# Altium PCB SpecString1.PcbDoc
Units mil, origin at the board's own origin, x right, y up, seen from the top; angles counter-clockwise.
Board outline 13135 x 12270 mil, 2 copper layers (Top Layer, Bottom Layer); 15 components, 16 nets, 35 pads, 6 vias.
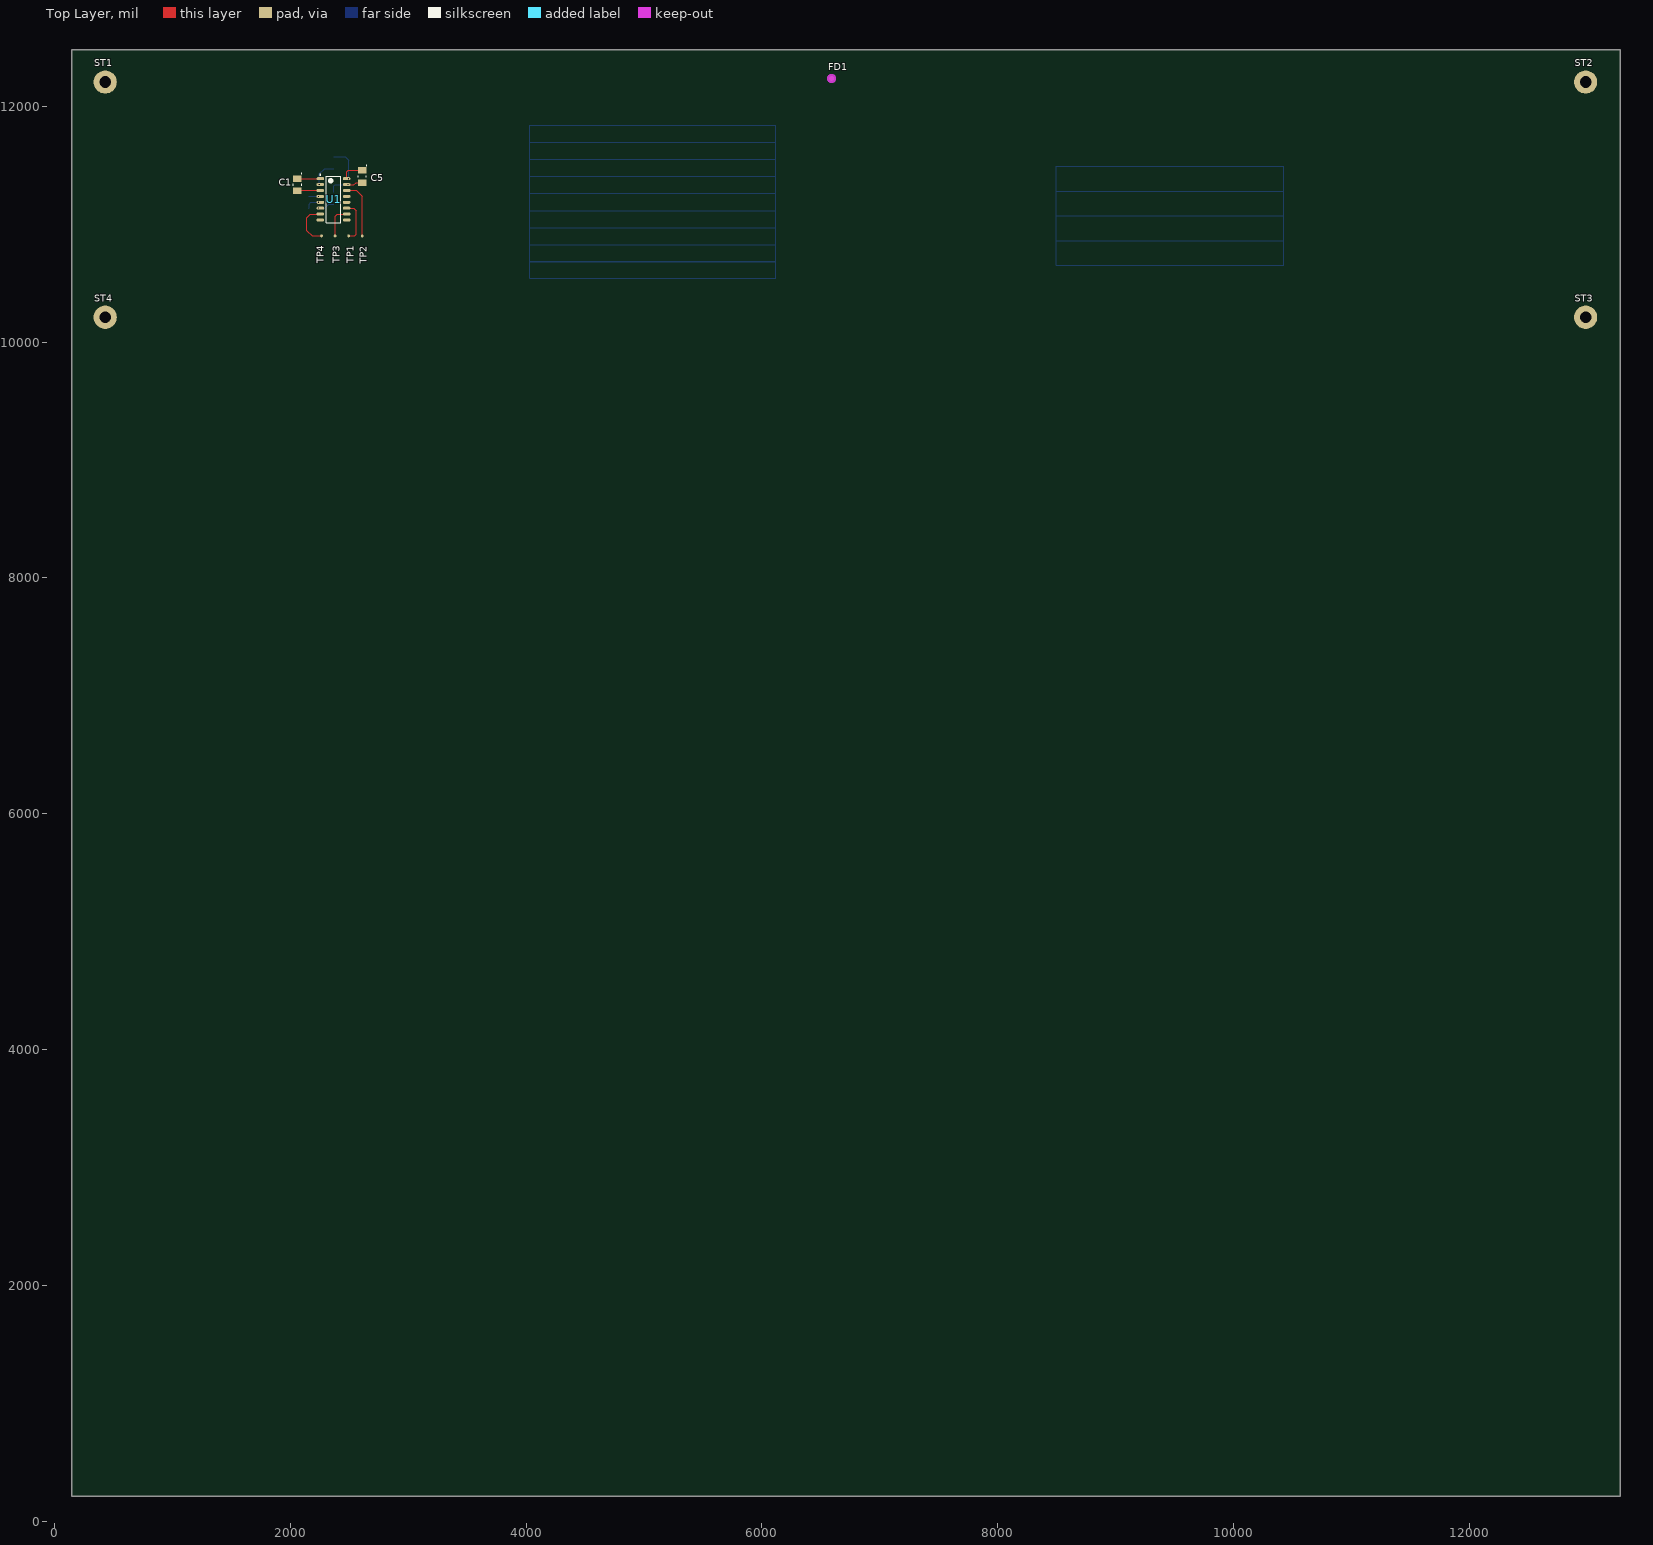
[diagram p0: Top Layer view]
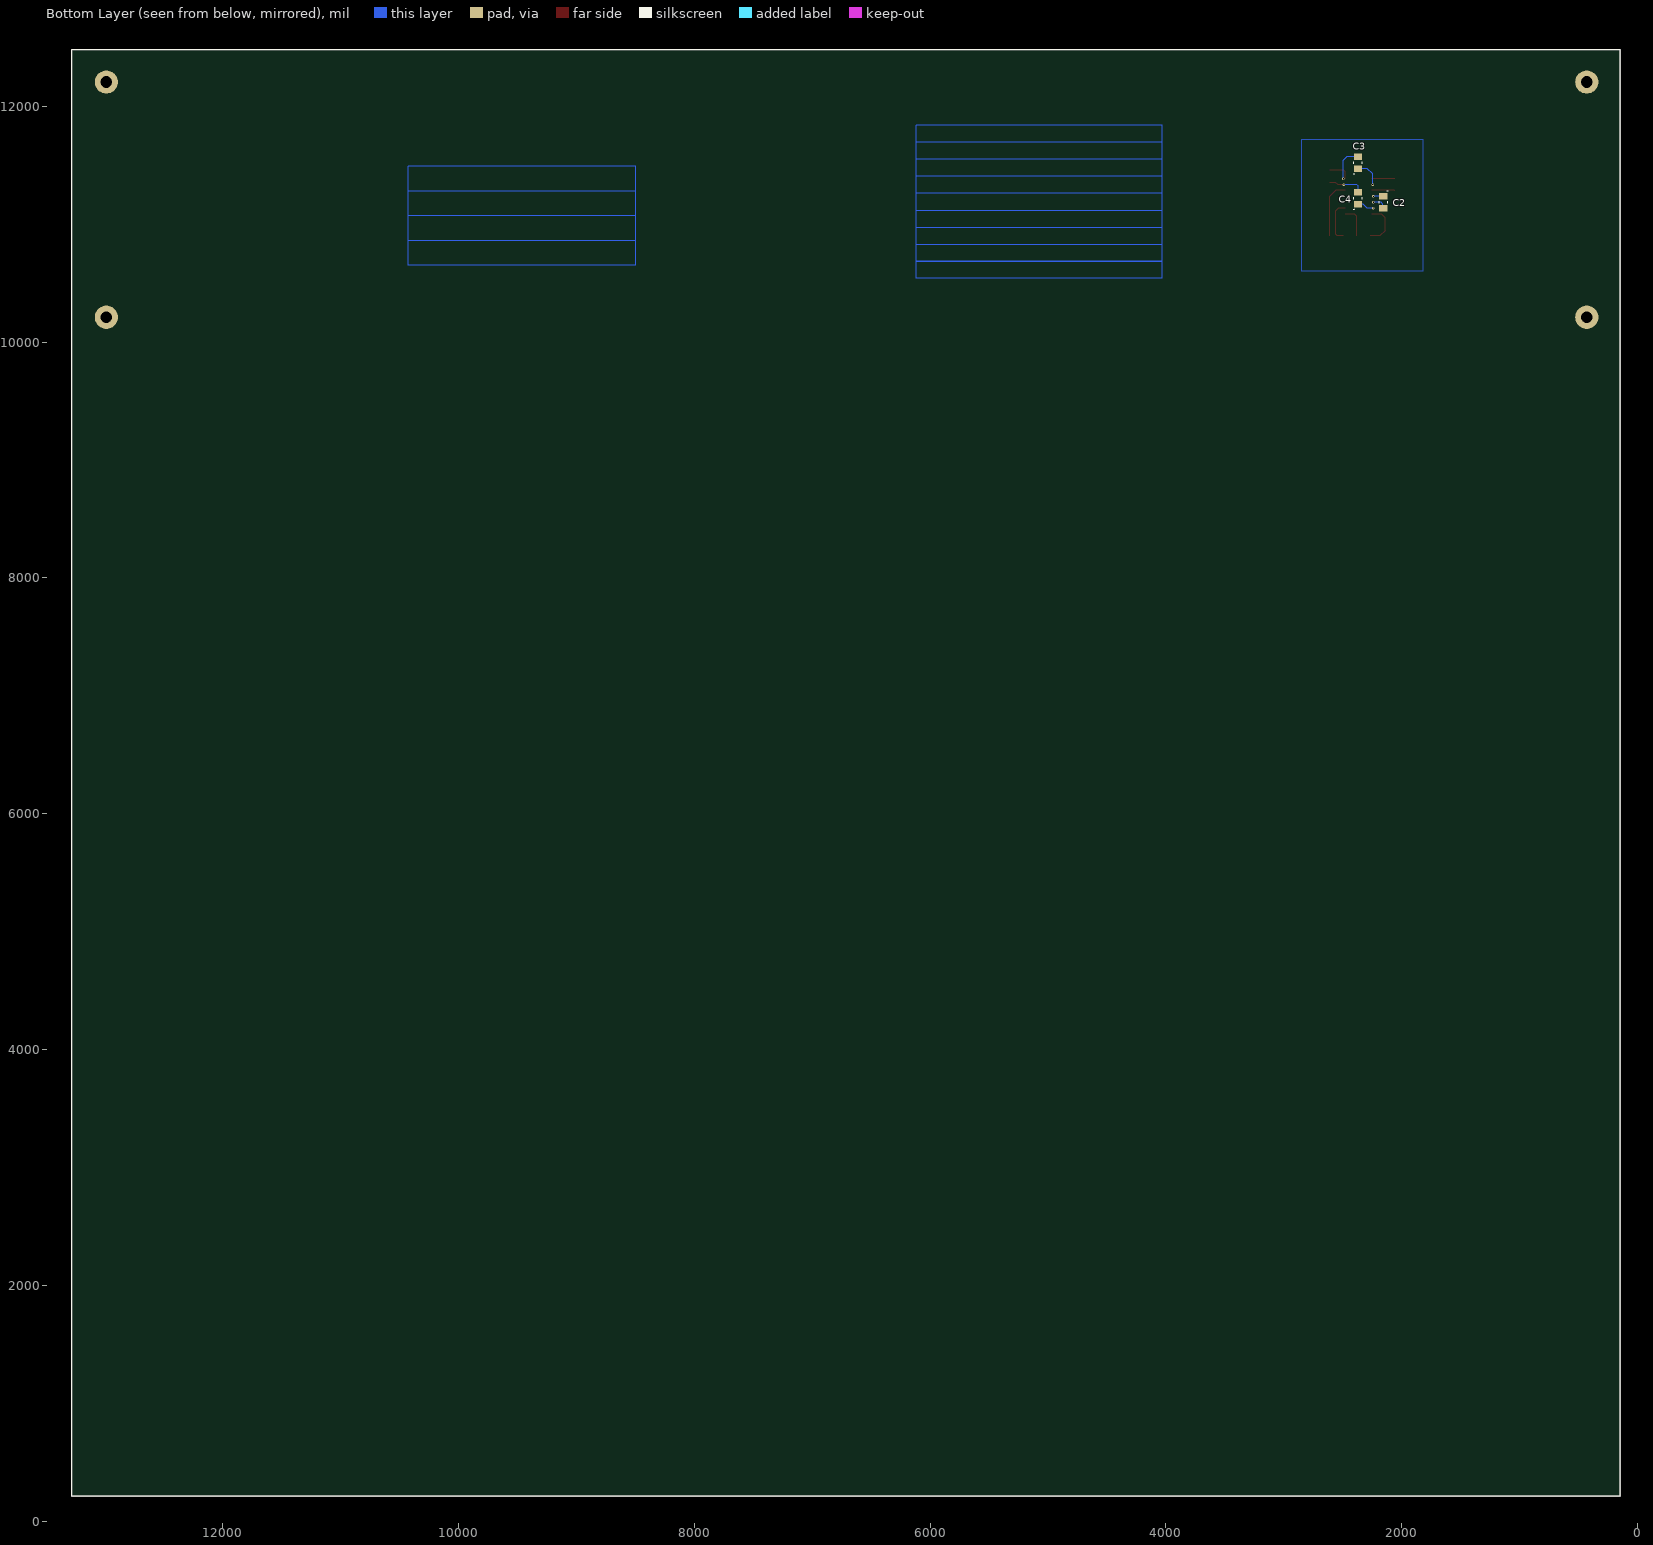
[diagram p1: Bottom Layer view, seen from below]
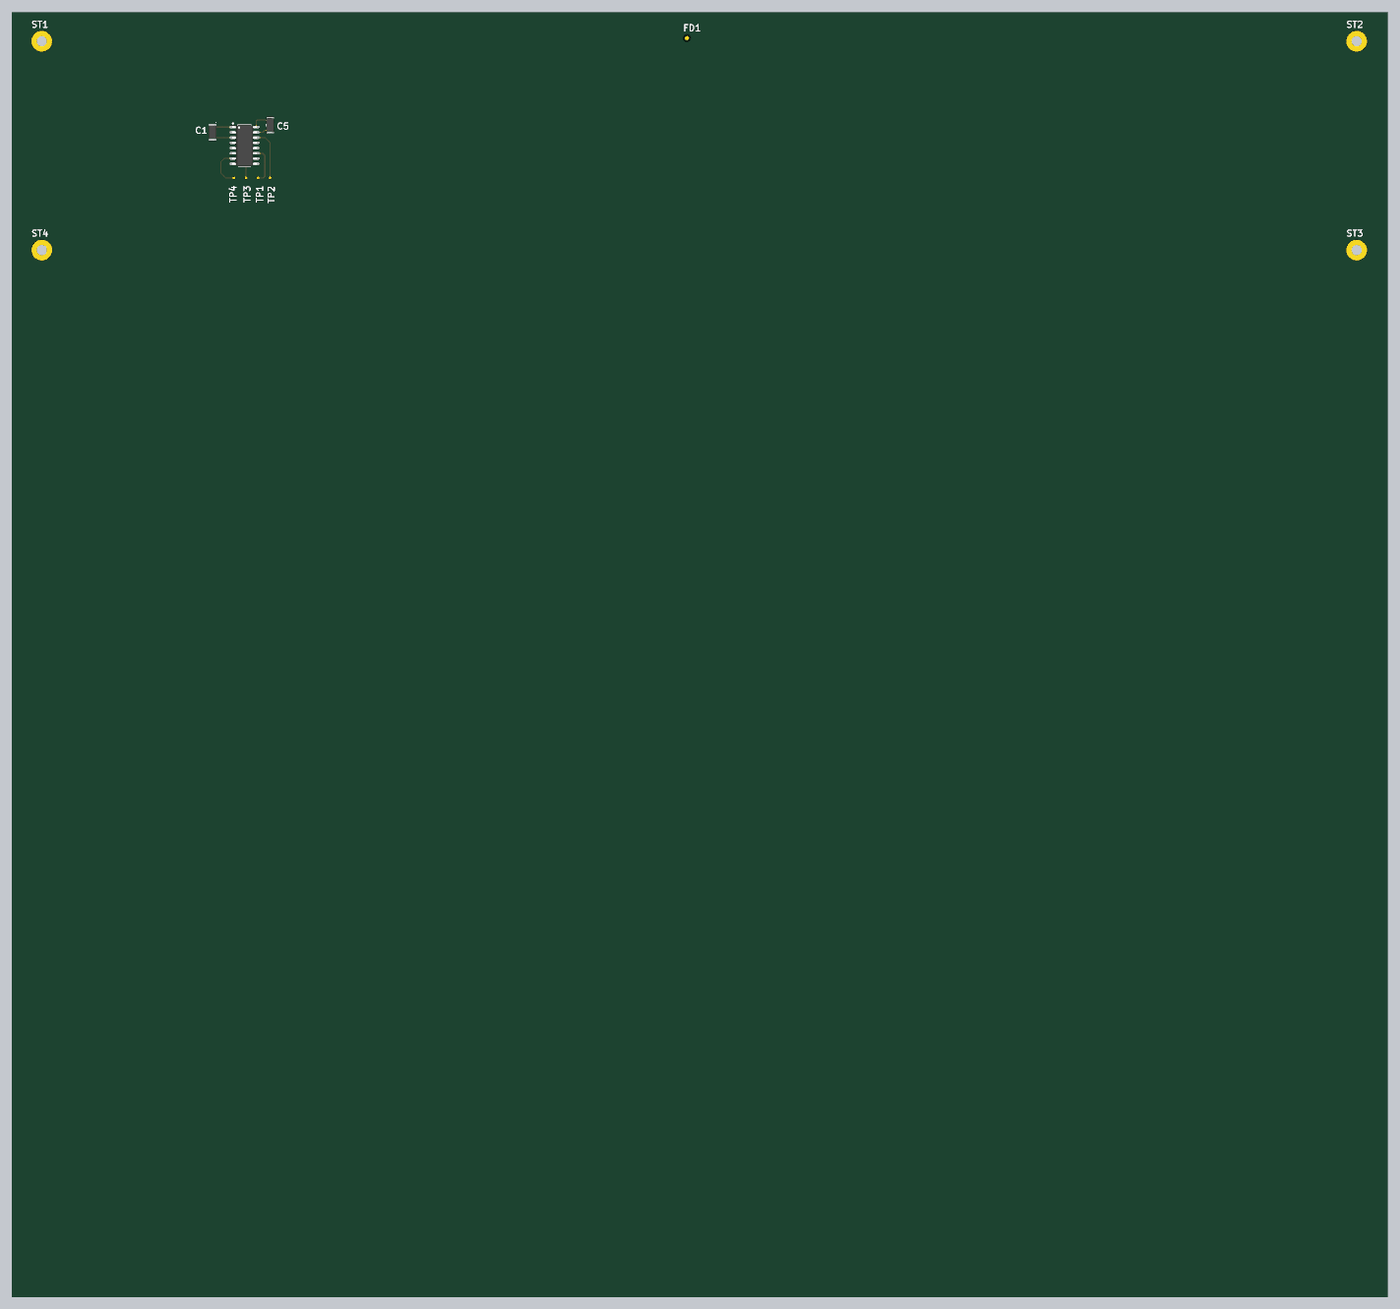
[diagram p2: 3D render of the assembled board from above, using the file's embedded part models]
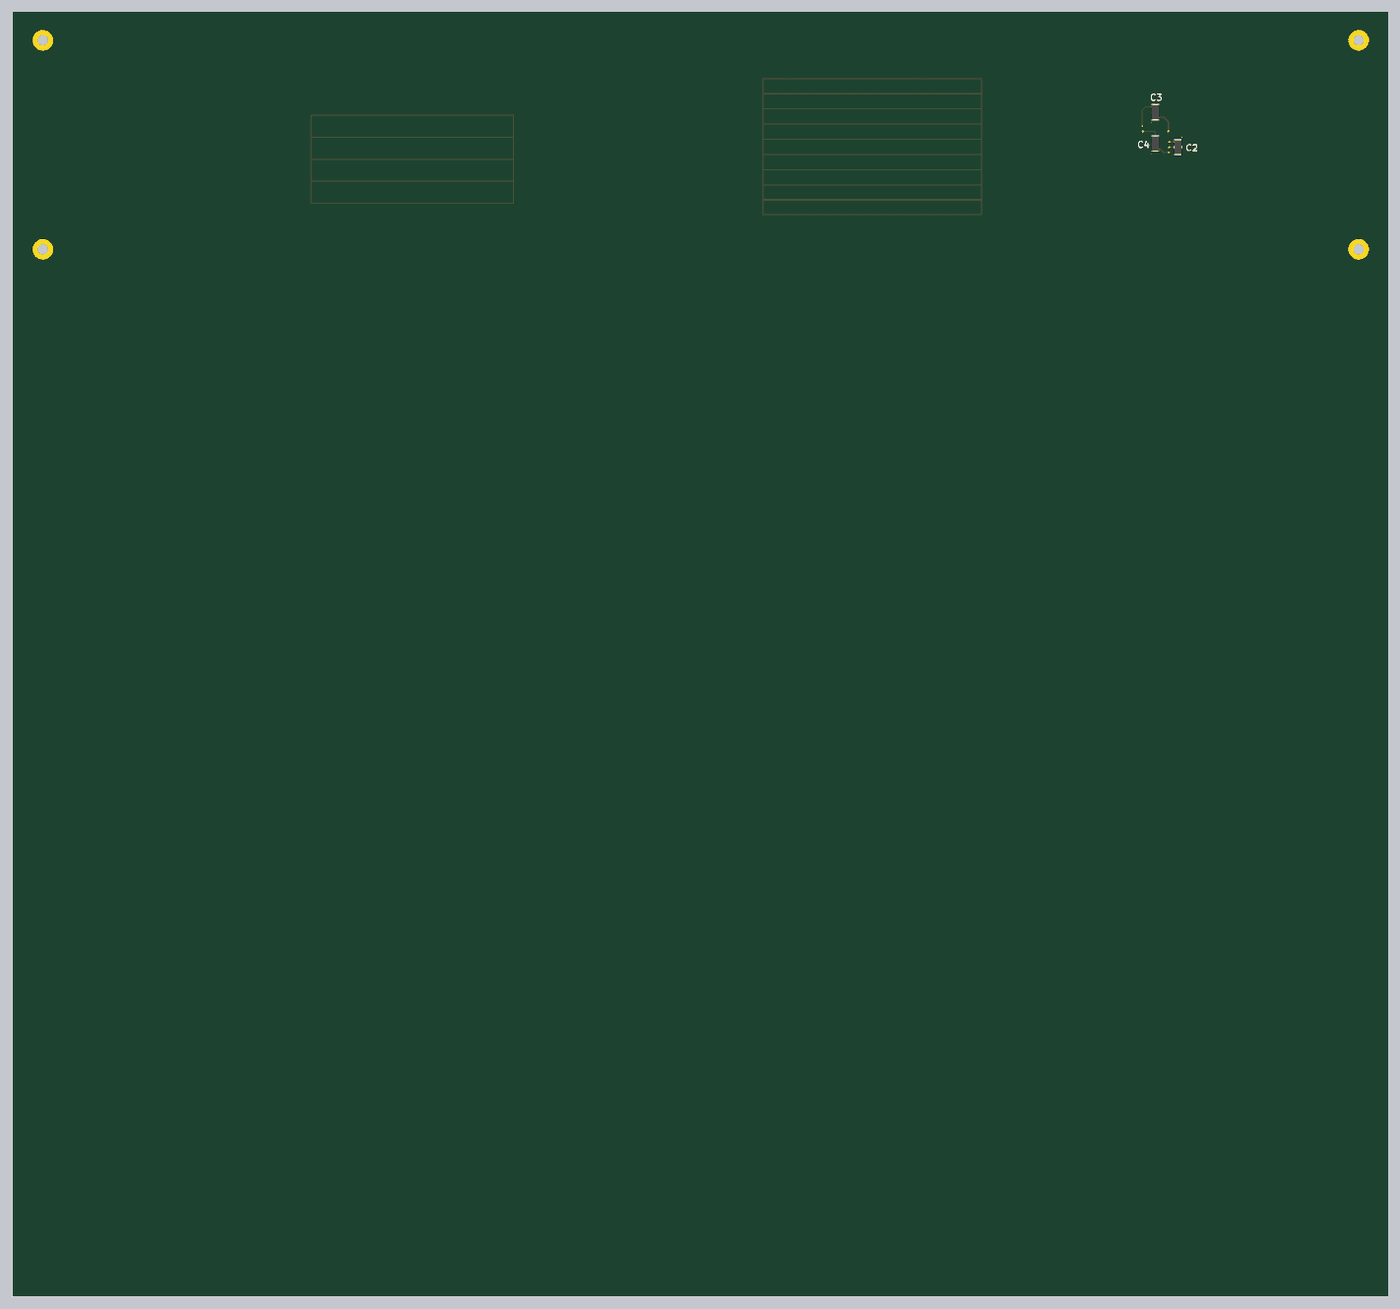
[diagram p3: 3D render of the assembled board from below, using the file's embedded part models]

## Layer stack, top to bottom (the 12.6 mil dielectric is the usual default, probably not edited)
Top Solder: solder mask 0.4, Solder Resist, Dk 3.5
Top Layer: signal copper 1.4
Dielectric 1: dielectric 12.6, FR-4, Dk 4.8
Bottom Layer: signal copper 1.4
Bottom Solder: solder mask 0.4, Solder Resist, Dk 3.5

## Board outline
145,210 145,12480 13280,12480 13280,210

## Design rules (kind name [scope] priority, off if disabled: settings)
Clearance [All] p1: gap=10 ignorepadtopadclearanceinfootprint=FALSE except(0: Arc-Hole Track-Hole SMDPad-Hole THPad-Hole Via-Hole Fill-Hole Poly-Hole Region-Hole Text-Hole)
PolygonConnect [All] p1: connectstyle=Relief reliefconductorwidth=10 reliefentries=4 polygonreliefangle="90 Angle" airgapwidth=10
RoutingVias [All] p1: holewidth=8 width=20 viastyle="Through Hole" minholewidth=6 minwidth=18 maxholewidth=12 maxwidth=50
SolderMaskExpansion [All] p1: expansion=4 istentingtop=FALSE
Width [All] p1: maxlimit=10 minlimit=10 preferedwidth=10
30 further rules are at their usual default settings.

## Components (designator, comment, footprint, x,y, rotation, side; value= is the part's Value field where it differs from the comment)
C1 "KYOCERA AVX-TAJA105K035RNJ" CAPMP3217X18-T_V 2060,11335 r270 top value=1µF
C2 "KYOCERA AVX-TAJA105K035RNJ" CAPMP3217X18-T_V 2155,11185 r270 bottom value=1µF
C3 "KYOCERA AVX-TAJA105K035RNJ" CAPMP3217X18-T_V 2370,11520 r90 bottom value=1µF
C4 "KYOCERA AVX-TAJA105K035RNJ" CAPMP3217X18-T_V 2370,11220 r90 bottom value=1µF
C5 "KYOCERA AVX-TAJA105K035RNJ" CAPMP3217X18-T_V 2610,11403.82 r270 top value=1µF
FD1 "FID1X2R" FID1X2R 6590,12235 r0 top
ST1 "PTH-M2D5X5" PTH-M2D5X5 430,12205 r0 top
ST2 "PTH-M2D5X5" PTH-M2D5X5 12985,12205 r0 top
ST3 "PTH-M2D5X5" PTH-M2D5X5 12985,10210 r0 top
ST4 "PTH-M2D5X5" PTH-M2D5X5 430,10210 r0 top
TP1 "TPAD6R" TP06R 2495,10900 r90 top
TP2 "TPAD6R" TP06R 2610,10900 r90 top
TP3 "TPAD6R" TP06R 2380,10900 r90 top
TP4 "TPAD6R" TP06R 2265,10900 r90 top
U1 "MAX232CSE+" MAXM-S16+5_M 2366.22,11210 r0 top

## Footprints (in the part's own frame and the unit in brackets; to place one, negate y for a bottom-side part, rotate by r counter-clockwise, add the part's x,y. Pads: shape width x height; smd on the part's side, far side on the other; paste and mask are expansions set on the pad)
CAPMP3217X18-T_V [mm] "Molded Capacitor, 2-Leads, Body 3.40x1.8mm"
  rect 1.4x1.8 smd: 1(-1.3,0) 2(1.3,0)
  silkscreen extent -2.45,-0.9 0.2,0.95, body extent -1.92,-0.9 1.92,0.9, height 1.8
FID1X2R [mm] "Fiducial - Round 1x2mm"
  round 1 smd paste-0.5 mask+0.5: 0(0,0)
  Top Layer keep-out circle w1: c0,0 r0.5
MAXM-S16+5_M [mm] "SOIC, 16-Leads, Body 10x4mm, Pitch 1.27mm, IPC Low Density"
  oval 1.65x0.65 smd: 1(-2.825,4.445) 2(-2.825,3.175) 3(-2.825,1.905) 4(-2.825,0.635) 5(-2.825,-0.635) 6(-2.825,-1.905) 7(-2.825,-3.175) 8(-2.825,-4.445) 9(2.825,-4.445) 10(2.825,-3.175) 11(2.825,-1.905) 12(2.825,-0.635) 13(2.825,0.635) 14(2.825,1.905) 15(2.825,3.175) 16(2.825,4.445)
  silkscreen extent -2.95,-5 1.6,5.44, body extent -3,-5 3,5, height 1.75
PTH-M2D5X5 [mm]
  round 5 hole 2.5: 1(0,0)
TP06R [mm] "Testpoint, round, d=0.6mm"
  round 0.6 smd paste-1: 1(0,0)

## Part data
C1 C2 C3 C4 C5: library part CMP-001-00040-7, "Standard Tantalum, 1 uF, +/- 10%, 35 V, -55 to 125 degC, 1206 (3216 Metric), RoHS, Tape and Reel", Capacitor Type=Tantalum, Case/Package=1206, Manufacturer=AVX, Max Operating Temperature=125°C, Min Operating Temperature=-55°C, Package Description="2-Pin Surface Mount Device, Body 3.2 x 1.65 mm", Package Quantity=2000, Package Reference=CAPMP3217X18-T, Resistance=7.5Ohm, Tolerance=10%, Voltage Rating=35V
FD1: library part CMP-00028-00005-1, "Fiducial - Round 1x2mm"
ST1 ST2 ST3 ST4: library part CMP-00028-00004-1, "M2 PTH (2.5mm), 5mm pad"
TP1 TP2 TP3 TP4: library part CMP-00028-00002-1, "0.6mm round"
U1: library part CMP-00024-00004-1, "Multichannel RS-232 Driver/Receiver, 5 V, 0 to 70 degC, 16-Pin SOIC (S16+3), RoHS, Tube", Case/Package=SOIC, Manufacturer=Maxim, Max Operating Temperature=70°C, Max Supply Voltage=5.5V, Min Operating Temperature=0°C, Min Supply Voltage=4.5V, Nominal Supply Current=10mA, Nominal Supply Voltage=5V, Package Description="16-Pin Small Outline Integrated Circuit, Body 9.9 x 3.9 mm, Pitch 1.27 mm", Package Quantity=50, Package Reference=S16+5, Package Version="Rev. G, 01/2016"

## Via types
v1: diameter 20, hole 8, Top Layer to Bottom Layer, 6 vias

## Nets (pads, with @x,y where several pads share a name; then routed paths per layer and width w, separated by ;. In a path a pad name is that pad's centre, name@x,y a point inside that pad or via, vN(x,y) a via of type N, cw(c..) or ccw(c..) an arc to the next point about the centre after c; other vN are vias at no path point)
+5V: C3.2 C5.1 U1.16 | length 488.1
  Top Layer w10: U1.16 2477.44,11442.44 2490,11455 C5.1
  Bottom Layer w10: C3.2 2371.18,11570 2465,11570 2495,11540 v1(2495,11385)
GND: C4.2 C5.2 U1.15 | length 317.8
  Top Layer w10: U1.15 v1(2490,11335) 2540,11335 2557.64,11352.64 C5.2
  Bottom Layer w10: C4.2 2370,11325 2380,11335 v1(2490,11335)
NetC1_1: C1.1 U1.1 | length 195.5
  Top Layer w10: C1.1 2061.18,11385 U1.1
NetC1_2: C1.2 U1.3 | length 195.5
  Top Layer w10: C1.2 2061.18,11285 U1.3
NetC2_1: C2.1 U1.4 | length 85.5
  Bottom Layer w10: C2.1 2156.18,11235 v1(2240,11235)
NetC2_2: C2.2 U1.5 | length 124.5
  Bottom Layer w10: C2.2 2160,11138.82 2160,11170 2175,11185 v1(2240,11185)
NetC3_1: C3.1 U1.2 | length 233.7
  Bottom Layer w10: v1(2245.6,11335.2) 2245.6,11425.6 2290,11470 2368.82,11470 C3.1
NetC4_1: C4.1 U1.6 | length 144
  Bottom Layer w10: v1(2240,11135) 2290,11135 2323.82,11168.82 C4.1
R1_In: U1.13
R1_Out: U1.12
R2_In: U1.8
R2_Out: U1.9
"T1 _In": TP1.1 U1.11 | length 362.1
  Top Layer w10: U1.11 2540,11135 2560,11115 2560,10915 2545,10900 TP1.1
T1_Out: TP2.1 U1.14 | length 488.3
  Top Layer w10: U1.14 2560,11285 2610,11235 TP2.1
T2_In: TP3.1 U1.10 | length 270.7
  Top Layer w10: TP3.1 2380,11065 2400,11085 U1.10
T2_Out: TP4.1 U1.7 | length 381.1
  Top Layer w10: U1.7 2170,11085 2140,11055 2140,10945 2185,10900 TP4.1
pads on no net: FD1.0 ST1.1 ST2.1 ST3.1 ST4.1
copper on no net: | length 57260
  Bottom Layer w10: 4030,10825 6115,10825 ; 4030,10825 4030,10970 ; 4030,10825 6115,10825 ; 4030,10825 4030,10680 6115,10680 6115,10825 ; 4030,10970 6115,10970 ; 4030,10970 4030,11115 ; 4030,10970 6115,10970 ; 4030,11115 6115,11115 ; 4030,11115 6115,11115 ; 4030,11115 4030,11260 ; 4030,11260 6115,11260 ; 4030,11260 4030,11405 ; 4030,11260 6115,11260 ; 4030,11405 6115,11405 ; 4030,11405 6115,11405 ; 4030,11405 4030,11550 ; 4030,11550 6115,11550 ; 4030,11550 4030,11695 ; 4030,11550 6115,11550 ; 4030,11695 6115,11695 ; 4030,11695 4030,11840 6115,11840 6115,11695 ; 4030,11695 6115,11695 ; 6115,10825 6115,10970 ; 6115,10970 6115,11115 ; 6115,11115 6115,11260 ; 6115,11260 6115,11405 ; 6115,11405 6115,11550 ; 6115,11550 6115,11695 ; 8495,10860 10425,10860 ; 8495,10860 8495,10650 10425,10650 10425,10860 ; 8495,10860 10425,10860 ; 8495,10860 8495,11070 ; 8495,11070 10425,11070 ; 8495,11070 8495,11280 ; 8495,11070 10425,11070 ; 8495,11280 10425,11280 ; 8495,11280 10425,11280 ; 8495,11280 8495,11490 10425,11490 10425,11280 ; 10425,10860 10425,11070 ; 10425,11070 10425,11280 ; 4030,10540 6115,10540 6115,10685 4030,10685 4030,10540

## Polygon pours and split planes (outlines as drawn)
GND on Bottom Layer "GND_L02_P000" (solid, pour order 0): 1815,11715 2850,11715 2850,10605 1815,10605

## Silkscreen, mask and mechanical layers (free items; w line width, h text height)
Bottom Overlay:
  lines w10: 145,210 13280,210 13280,12480 145,12480 145,210 ; 145,2310 145,2325 145,2310
Mechanical 1:
  drawing of 816 lines, arcs and shapes, not listed
  text "Value" at 2810,9980 h60
  text "Notes" at 7480,9980 h60
  text "String Name" at 1279.73,9969.99 h60
  text "Application_BuildNumber" at 944.84,9839.99 h60
  text ".Application_BuildNumber" at 2800,9840 h60
  text "Revision of Altium Used" at 7350,9840 h60
  text "Arc_Count" at 1339.72,9700 h60
  text ".Arc_Count" at 2800,9700 h60
  text "The number of arcs on the PCB" at 7350,9700 h60
  text "BlindVia_Count" at 1210,9560 h60
  text ".BlindVia_Count" at 2800,9560 h60
  text "The number of blind vias on the PCB" at 7350,9560 h60
  text "The vertical size of the PCB" at 7350,9430 h60
  text "Board_Height" at 1250,9419.99 h60
  text ".Board_Height" at 2800,9420 h60
  text "Board_Width" at 1280,9280 h60
  text ".Board_Width" at 2800,9280 h60
  text "The horizontal size of the PCB" at 7350,9280 h60
  text "BuriedVia_Count" at 1170,9140 h60
  text ".BuriedVia_Count" at 2800,9140 h60
  text "The number of buried vias on the PCB" at 7350,9140 h60
  text "CageCode" at 1359.71,8999.99 h60
  text ".CageCode" at 2800,9000 h60
  text "The cage code" at 7350,8999.99 h60
  text "Comment" at 1399.7,8860 h60
  text "The comment string for a component" at 7350,8859.99 h60
  text ".Comment" at 2800,8850 h60
  text "Component_Count" at 1164.77,8719.99 h60
  text ".Component_Count" at 2800,8720 h60
  text "The number of components on the PCB" at 7350,8719.99 h60
  text "ComponentMixed_Count" at 1019.82,8579.99 h60
  text ".ComponentMixed_Count" at 2800,8580 h60
  text "The number of components with mixed pads on the PCB" at 7350,8579.99 h60
  text "The number of components with SMD pads on the PCB" at 7350,8449.99 h60
  text "ComponentSMD_Count" at 1074.8,8439.99 h60
  text ".ComponentSMD_Count" at 2800,8440 h60
  text "ComponentThru_Count" at 1044.81,8299.99 h60
  text ".ComponentThru_Count" at 2800,8300 h60
  text "The number of components with thru-hole pads on the PCB" at 7350,8299.99 h60
  text "ComputerName" at 1244.75,8159.99 h60
  text ".ComputerName" at 2800,8160 h60
  text "The name of the computer which had the SW" at 7350,8159.99 h60
  text "CopperInner_Weight_Max" at 954.84,8020.84 h60
  text ".CopperInner_Weight_Max" at 2800,8020 h60
  text "The maximum weight of copper on inner layers" at 7350,8009.99 h60
  text "CopperOuter_Weight_Max" at 954.84,7880.84 h60
  text ".CopperOuter_Weight_Max" at 2800,7880 h60
  text "The maximum weight of copper on outer layers" at 7350,7879.99 h60
  text "Designator" at 1320,7739.99 h60
  text ".Designator" at 2800,7739.99 h60
  text "The designator string for a component" at 7350,7739.99 h60
  text "Fill_Count" at 1324.72,7602.65 h60
  text ".Fill_Count" at 2800,7600 h60
  text "The number of fills on the PCB" at 7350,7600 h60
  text "Hole_Count" at 1314.72,7460 h60
  text ".Hole_Count" at 2800,7460 h60
  text "The number of drill holes on the PCB" at 7350,7460 h60
  text "Hole_Size_Min" at 1230,7320 h60
  text ".Hole_Size_Min" at 2800,7320 h60
  text "The minimum hole diamter on the PCB" at 7350,7320 h60
  text "Hole_Size_Num" at 1219.75,7180 h60
  text ".Hole_Size_Num" at 2800,7180 h60
  text "The number of unique hole diameters on the PCB" at 7350,7179.99 h60
  text ".Item" at 2800,7050 h60
  text "Item" at 1480,7040 h60
  text "The item that the generated data relates to" at 7350,7029.99 h60
  text "ItemAndRevision" at 1170,6900 h60
  text ".ItemAndRevision" at 2800,6900 h60
  text "The item and specific revision of that Item that the generated data relates to" at 7350,6899.99 h60
  text "ItemRevision" at 1260,6760 h60
  text ".ItemRevision" at 2800,6760 h60
  text "The specific revision of the Item that the generated data relates to" at 7350,6759.99 h60
  text "ItemRevisionBase" at 1140,6620 h60
  text ".ItemRevisionBase" at 2800,6620 h60
  text "The Base Level portion of an Item Revision's naming scheme" at 7350,6619.99 h60
  text "ItemRevisionLevel1" at 1094.79,6473.49 h60
  text ".ItemRevisionLevel1" at 2800,6473.49 h60
  text "The Level 1 portion of an Item Revision's naming scheme" at 7350,6469.99 h60
  text "ItemRevisionLevel1AndBase" at 879.86,6335.29 h60
  text ".ItemRevisionLevel1AndBase" at 2800,6335.29 h60
  text "The Level 1 and Base Level portions of an Item Revision's naming scheme" at 7350,6329.99 h60
  text "ItemRevisionLevel2" at 1084.8,6197.1 h60
  text ".ItemRevisionLevel2" at 2800,6197.1 h60
  text "The Level 2 portion of an Item Revision's naming scheme" at 7350,6189.99 h60
  text "ItemRevisionLevel2AndLevel1" at 829.88,6058.9 h60
  text ".ItemRevisionLevel2AndLevel1" at 2800,6058.9 h60
  text "The Level 2 and Level 1 portions of an Item Revision's naming scheme" at 7350,6049.99 h60
  text "Layer_Count" at 1279.73,5923.75 h60
  text ".Layer_Count" at 2800,5923.76 h60
  text "The number of copper layers on the PCB" at 7350,5919.99 h60
  text "Layer_ID" at 1350,5779.99 h60
  text "The ID of the layer on which the string is placed" at 7350,5779.99 h60
  text ".Layer_ID" at 2800,5770 h60
  text "Layer_Name" at 1290,5639.99 h60
  text "The name of the layer on which the string is placed" at 7350,5639.99 h60
  text ".Layer_Name" at 2800,5630 h60
  text "Legend" at 1410,5509.99 h60
  text ".Legend" at 2800,5499.99 h60
  text "A symbol legend for mechanical drill plots." at 7350,5499.99 h60
  text "MicroVia_Count" at 1210,5360 h60
  text ".MicroVia_Count" at 2800,5360 h60
  text "The number of microvias on the PCB" at 7350,5360 h60
  text "Automatically populated" at 7350,5229.99 h60
  text "ModifiedDate" at 1260,5220 h60
  text ".ModifiedDate" at 2800,5220 h60
  text "Automatically populated" at 7350,5089.99 h60
  text "ModifiedTime" at 1260,5080 h60
  text ".ModifiedTime" at 2800,5070 h60
  text "Net_Count" at 1340,4940 h60
  text ".Net_Count" at 2800,4940 h60
  text "The total number of different nets on the PCB" at 7350,4940 h60
  text "Net_Names_On_Layer" at 1070,4799.99 h60
  text ".Net_Names_On_Layer" at 2800,4799.99 h60
  text "The names of all nets on the specific layer" at 7350,4799.99 h60
  text "Pad_Count" at 1339.72,4670 h60
  text "The number of pads on the PCB" at 7350,4669.99 h60
  text ".Pad_Count" at 2800,4660 h60
  text "The number of SMD pads on the PCB" at 7350,4519.99 h60
  text ".PadSMD_Count" at 2790,4510 h60
  text "PadSMD_Count" at 1240,4500 h60
  text "PadThru_Count" at 1220,4380 h60
  text ".PadThru_Count" at 2800,4380 h60
  text "The number of thru-hole pads on the PCB" at 7350,4379.99 h60
  text ".Pattern" at 2800,4250 h60
  text "Pattern" at 1399.7,4240 h60
  text "The names of the component footprints used on the PCB" at 7350,4239.99 h60
  text "Pcb_File_Name" at 1219.75,4110 h60
  text ".Pcb_File_Name" at 2800,4099.99 h60
  text "The PCB's path and file name" at 7350,4099.99 h60
  text "The file name of the PCB document" at 7350,3970 h60
  text "Pcb_File_Name_No_Path" at 984.83,3960 h60
  text ".Pcb_File_Name_No_Path" at 2800,3959.99 h60
  text "PCBConfigurationName" at 1020,3819.99 h60
  text ".PCBConfigurationName" at 2790,3820 h60
  text "The name of the data set from which the output has been generated" at 7350,3819.99 h60
  text "Plot_File_Name" at 1199.76,3680 h60
  text ".Plot_File_Name" at 2800,3679.99 h60
  text "The file name of the Gerber plot file" at 7350,3679.99 h60
  text ".Poly_Count" at 2800,3550 h60
  text "The number of polygons on the PCB" at 7350,3549.99 h60
  text "Poly_Count" at 1314.72,3539.99 h60
  text ".Print_Date" at 2800,3410 h60
  text "The date of printing (automatically populated)" at 7350,3409.99 h60
  text "Print_Date" at 1314.72,3400 h60
  text "The printing/plot scale factor (automatically populated)" at 7350,3269.99 h60
  text "Print_Scale" at 1284.73,3260 h60
  text ".Print_Scale" at 2800,3260 h60
  text "Print_Time" at 1314.72,3130 h60
  text "The time of printing/plotting (automatically populated)" at 7350,3129.99 h60
  text ".Print_Time" at 2800,3120 h60
  text "The name of the printout" at 7350,2989.99 h60
  text "Printout_Name" at 1224.75,2980 h60
  text ".Printout_Name" at 2800,2979.99 h60
  text "SlotHole_Count" at 1204.76,2840 h60
  text ".SlotHole_Count" at 2800,2840 h60
  text "The number of slotted holes on the PCB" at 7350,2840 h60
  text ".SolderMask_Bottom" at 2800,2710 h60
  text "SolderMask_Bottom" at 1104.79,2700 h60
  text "The availablity of bottom solder mask" at 7350,2699.99 h60
  text "SolderMask_Top" at 1200,2559.99 h60
  text ".SolderMask_Top" at 2800,2560 h60
  text "The availablity of top solder mask" at 7350,2559.99 h60
  text "The number of square holes on the PCB" at 7350,2429.99 h60
  text "SquareHole_Count" at 1134.78,2419.99 h60
  text ".SquareHole_Count" at 2800,2410 h60
  text "StackedVia_Count" at 1139.78,2280 h60
  text ".StackedVia_Count" at 2800,2280 h60
  text "The number of stacked vias on the PCB" at 7350,2278.6 h60
  text "String_Count" at 1280,2139.99 h60
  text ".String_Count" at 2800,2140 h60
  text "The number of strings on the PCB" at 7350,2139.99 h60
  text "The number of thru-hole vias on the PCB" at 7350,2008.6 h60
  text "Thru_Via_Count" at 1200,2000 h60
  text ".Thru_Via_Count" at 2800,2000 h60
  text "Total_Thickness" at 1164.77,1860 h60
  text ".Total_Thickness" at 2800,1860 h60
  text "The thickness of the board" at 7350,1860 h60
  text ".Total_Thickness(Board Layer Stack)" at 2800,1720 h60
  text "The thickness of the board layer stack" at 7350,1719.99 h60
  text "Total_Thickness(Board Layer Stack)" at 614.95,1709.99 h60
  text "Track_Count" at 1280,1580 h60
  text ".Track_Count" at 2800,1580 h60
  text "The number of tracks on the PCB" at 7350,1580 h60
  text "VariantName" at 1280,1450 h60
  text ".VariantName" at 2800,1440 h60
  text "The variant of the design from which the output has been created" at 7350,1439.99 h60
  text ".VersionControl_PrjFolderRevNumber" at 2800,1310 h60
  text "The current revision number of the project" at 7350,1299.99 h60
  text "VersionControl_ProjFolderRevNumber" at 604.95,1289.99 h60
  text "VersionControl_ProjFolderRevNumber" at 604.95,1159.99 h60
  text ".VersionControl_PrjFolderRevNumber" at 2800,1160 h60
  text "The current revision number of the document" at 7350,1160 h60
  text "The current revision number of the document" at 7350,1030 h60
  text "VersionControl_ProjFolderRevNumberShort" at 460,1019.99 h60
  text ".VersionControl_ProjFolderRevNumberShort" at 2800,1020 h60
  text "VersionControl_RevNumber" at 899.86,880 h60
  text ".VersionControl_RevNumber" at 2800,879.99 h60
  text "The current revision number of the document" at 7350,880 h60
  text "The current revision number of the document" at 7350,750 h60
  text "VersionControl_RevNumberShort" at 754.9,740 h60
  text ".VersionControl_RevNumberShort" at 2800,739.99 h60
  text ".Via_Count" at 2820,610 h60
  text "The number of vias on the PCB" at 7350,610 h60
  text "Via_Count" at 1344.71,600 h60
Mechanical 13:
  text ".Arc_Count" at 6250,11740 h60
  text "Number of Arcs" at 4674.82,11730 h60
  text ".Arc_Count" at 5650,11730 h60
  text ".Component_Count" at 6250,11599.99 h60
  text ".Component_Count" at 5650,11585 h60
  text "Number of Components" at 4324.94,11568.34 h60
  text ".Fill_Count" at 5650,11440 h60
  text ".Fill_Count" at 6250,11440 h60
  text "Number of Fills" at 4644.83,11426.67 h60
  text "Design Tool" at 8610,11344.99 h60
  text "Altium Designer" at 9560,11339.99 h60
  text ".Hole_Count" at 5650,11295 h60
  text ".Hole_Count" at 6250,11295 h60
  text "Number of Drill Holes" at 4294.94,11285 h60
  text ".Net_Count" at 5650,11150 h60
  text ".Net_Count" at 6250,11150 h60
  text "Number of Different Nets" at 4125,11143.34 h60
  text "Version" at 8615,11143.33 h60
  text ".Application_BuildNumber" at 9560,11138.33 h60
  text ".Application_BuildNumber" at 10485,11134.99 h60
  text ".Pad_Count" at 6250,11015 h60
  text ".Pad_Count" at 5650,11005 h60
  text "Number of Pads" at 4674.82,11001.67 h60
  text "Modified Date" at 8610,10941.66 h60
  text ".ModifiedDate" at 9560,10936.66 h60
  text ".ModifiedDate" at 10485,10925 h60
  text ".Via_Count" at 6250,10870 h60
  text "Number of Vias" at 4684.82,10860 h60
  text ".Via_Count" at 5650,10860 h60
  text "Modified Time" at 8605,10740 h60
  text ".ModifiedTime" at 9560,10735 h60
  text "Number of Polygons" at 4450,10724.99 h60
  text ".Poly_Count" at 6250,10724.99 h60
  text ".Poly_Count" at 5650,10720 h60
  text ".ModifiedTime" at 10485,10710 h60
  text ".Total_Thickness" at 6250,10585 h60
  text "Board Thickness" at 4615,10575 h60
  text ".Total_Thickness" at 5650,10575 h60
